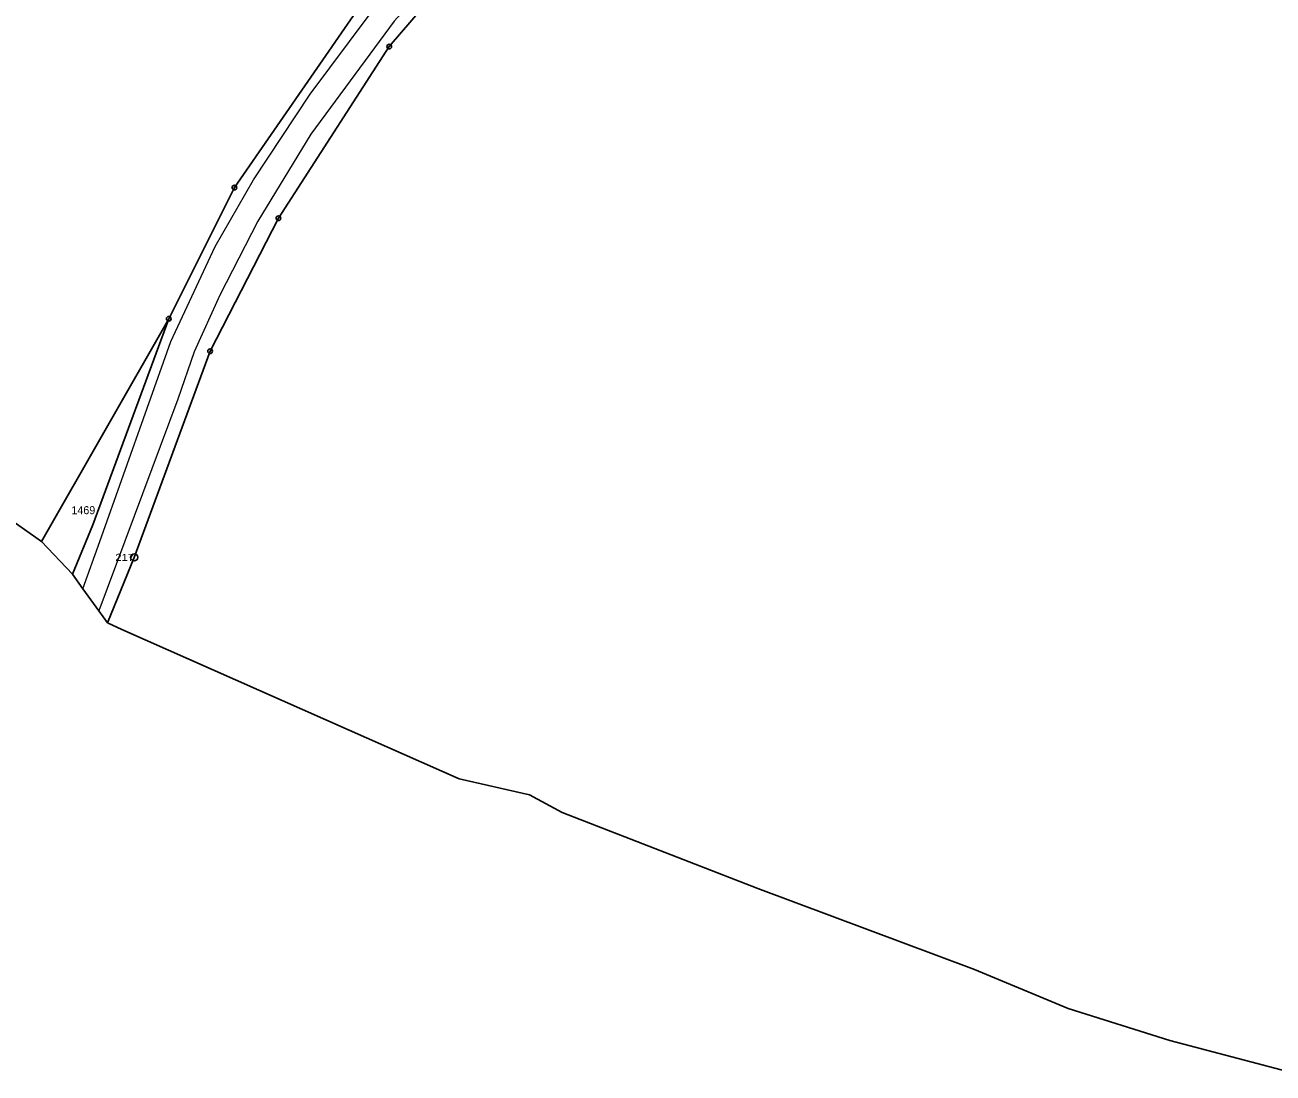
# Model space of a CAD drawing. Extents: x -872229 to -869198, y -1075981 to -1074329.
# Drawn here: x -871472.2 to -871207, y -1075817.5 to -1075594.7 of the extents above; entities that cross this region are included whole.
import ezdxf
from ezdxf.enums import TextEntityAlignment as Align

# ---------------------------------------------------------------- set-up
doc = ezdxf.new("R2010")
doc.units = 0
doc.header["$LTSCALE"] = 0.68
for name, color, linetype, lineweight in [('1', 7, 'Continuous', 25), ('4', 7, 'Continuous', 13), ('8', 7, 'Continuous', 25)]:
    doc.layers.add(name, color=color, linetype=linetype, lineweight=lineweight)
doc.layers.add('2', color=7, linetype='Continuous')

msp = doc.modelspace()

# ---------------------------------------------------------------- linework, layer by layer
at = {"layer": '1'}
for p, q in [((-871462.11, -1075711.44), (-871468.69, -1075704.44)), ((-871451.56, -1075723.14), (-871454.61, -1075721.79)), ((-871228.89, -1075810.51), (-871202.55, -1075817.46))]:
    msp.add_line(p, q, dxfattribs=at)
for points in [[(-871212.24, -1075392.84), (-871252.68, -1075434.13), (-871377.15, -1075563.45), (-871402.35, -1075592.63), (-871427.67, -1075629.24), (-871441.61, -1075657.13), (-871468.69, -1075704.44)], [(-871309.29, -1075507.4), (-871370.19, -1075570.62), (-871394.77, -1075599.26), (-871418.31, -1075635.76), (-871432.83, -1075664.02), (-871448.97, -1075707.84), (-871454.61, -1075721.79)], [(-871468.69, -1075704.44), (-871508.48, -1075676.4), (-871526.27, -1075654.51), (-871546.4, -1075620.32), (-871556.03, -1075596.19)], [(-871441.61, -1075657.13), (-871457.75, -1075700.95), (-871462.11, -1075711.44)], [(-871454.61, -1075721.79), (-871456.47, -1075719.22), (-871459.85, -1075714.56), (-871462.11, -1075711.44)], [(-871451.56, -1075723.14), (-871403.27, -1075744.54), (-871379.92, -1075754.89)], [(-871379.92, -1075754.89), (-871364.99, -1075758.34), (-871358.07, -1075762.05)], [(-871358.07, -1075762.05), (-871316.43, -1075778.25), (-871270.44, -1075795.48)], [(-871270.44, -1075795.48), (-871250.55, -1075803.77), (-871228.89, -1075810.51)]]:
    msp.add_lwpolyline(points, dxfattribs=at)
at = {"layer": '4'}
for p, q in [((-871431.74, -1075641.73), (-871423.61, -1075627.58)), ((-871422.7, -1075636.35), (-871430.78, -1075652.09)), ((-871441.17, -1075661.93), (-871431.74, -1075641.73)), ((-871456.27, -1075704.47), (-871441.17, -1075661.93)), ((-871439.7, -1075674.21), (-871456.47, -1075719.22)), ((-871459.85, -1075714.56), (-871456.27, -1075704.47))]:
    msp.add_line(p, q, dxfattribs=at)
for points in [[(-871370.95, -1075568.72), (-871393.73, -1075593.84), (-871411.43, -1075617.88), (-871422.7, -1075636.35)], [(-871423.61, -1075627.58), (-871411.59, -1075609.37), (-871394.86, -1075586.88)], [(-871430.78, -1075652.09), (-871436.26, -1075664.18), (-871439.7, -1075674.21)]]:
    msp.add_lwpolyline(points, dxfattribs=at)
at = {"layer": '8'}
for centre, radius in [((-871394.77, -1075599.2599), 0.5), ((-871394.77, -1075599.2599), 0.0303), ((-871427.67, -1075629.2399), 0.5), ((-871427.67, -1075629.2399), 0.0303), ((-871418.31, -1075635.7599), 0.5), ((-871418.31, -1075635.7599), 0.0303), ((-871441.61, -1075657.1299), 0.5), ((-871441.61, -1075657.1299), 0.0303), ((-871432.83, -1075664.0199), 0.5), ((-871432.83, -1075664.0199), 0.0303), ((-871448.97, -1075707.8398), 0.75), ((-871448.97, -1075707.8398), 0.03)]:
    msp.add_circle(centre, radius, dxfattribs=at)

# ---------------------------------------------------------------- texts
at = {"layer": '2'}
msp.add_text('1469', height=1.7, dxfattribs=at).set_placement((-871462.3, -1075698.66))
at = {"layer": '8', "width": 1.2}
msp.add_text('217', height=1.5, dxfattribs=at).set_placement((-871448.97, -1075708.59), align=Align.RIGHT)

doc.saveas('drawing.dxf')
